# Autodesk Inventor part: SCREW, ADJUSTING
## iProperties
Title: SCREW, ADJUSTING
Author: E. MOSS
Revision Number: A
Shininess: 41.0
PropertySet Name: _Private Model Information
Created: 2000-11
Part Number: S10-3
Project: ACME
Description: SCREW, ADJUSTING
Document SubType Name: Modeling
Designer: Administrator
Control State: 0
Master: False
Checked Out: False
PropertySet Name: Design Tracking Control
Density: 0.0
Volumn: 0.0
Area: 0.0
PropertySet Name: Model Information
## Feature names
1. Extrusion1
2. Extrusion2
3. Chamfer1
4. Extrusion3
5. Extrusion4
6. Hole1
